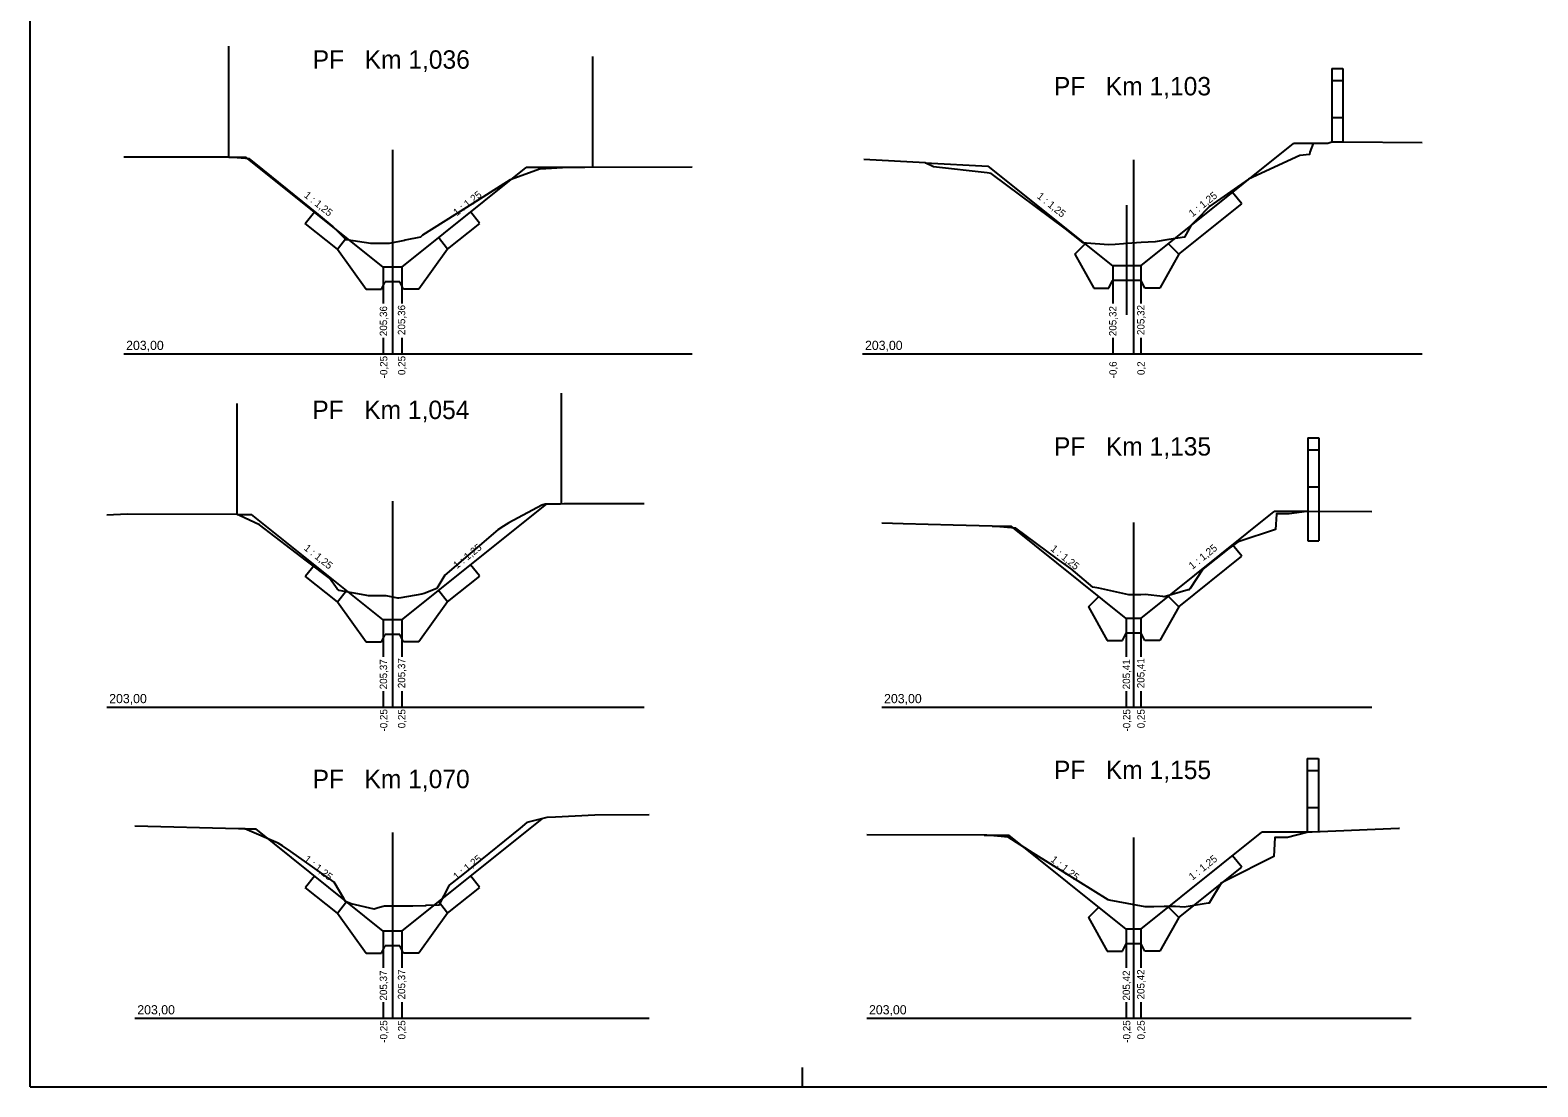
# Model space of a CAD drawing. Extents: x -547174 to -543113, y -1125006 to -1123643.
# Drawn here: x -547152.27 to -547111.27, y -1123769.75 to -1123741.01 of the extents above; entities that cross this region are included whole.
import ezdxf

# ---------------------------------------------------------------- set-up
doc = ezdxf.new("R2010")
doc.units = 0
for name, color, linetype in [('Default', 7, 'Continuous'), ('Profile', 7, 'Continuous'), ('PROFILY NÁVRH', 7, 'Continuous'), ('Section', 7, 'Continuous'), ('STANIČENÍ', 7, 'Continuous')]:
    doc.layers.add(name, color=color, linetype=linetype)

msp = doc.modelspace()

# ---------------------------------------------------------------- linework, layer by layer
at = {"layer": 'Default'}
for points in [[(-547114.415, -1123744.079), (-547116.565, -1123744.061), (-547116.619, -1123744.061), (-547116.866, -1123744.059), (-547116.98, -1123744.096), (-547117.029, -1123744.097), (-547117.326, -1123744.097), (-547117.379, -1123744.096), (-547117.467, -1123744.334), (-547117.474, -1123744.398), (-547117.736, -1123744.425), (-547119.135, -1123745.069), (-547120.184, -1123745.8), (-547120.559, -1123746.178), (-547120.699, -1123746.318), (-547120.699, -1123746.318), (-547120.879, -1123746.645), (-547121.301, -1123746.708), (-547121.679, -1123746.765), (-547122.055, -1123746.792), (-547122.311, -1123746.81), (-547122.762, -1123746.842), (-547122.944, -1123746.855), (-547123.545, -1123746.803), (-547123.636, -1123746.796), (-547124.109, -1123746.415), (-547126.133, -1123744.908), (-547126.247, -1123744.89), (-547127.702, -1123744.732), (-547127.934, -1123744.619), (-547129.597, -1123744.529)], [(-547134.27, -1123744.742), (-547137.186, -1123744.745), (-547137.639, -1123744.746), (-547138.405, -1123744.792), (-547138.416, -1123744.792), (-547139.192, -1123745.073), (-547139.219, -1123745.087), (-547140.407, -1123745.838), (-547141.599, -1123746.592), (-547141.637, -1123746.624), (-547141.643, -1123746.634), (-547141.652, -1123746.638), (-547142.07, -1123746.726), (-547142.087, -1123746.729), (-547142.504, -1123746.817), (-547142.719, -1123746.816), (-547142.727, -1123746.815), (-547142.737, -1123746.815), (-547143.005, -1123746.815), (-547143.671, -1123746.716), (-547143.676, -1123746.715), (-547144.032, -1123746.357), (-547144.034, -1123746.355), (-547144.061, -1123746.335), (-547144.433, -1123746.023), (-547146.132, -1123744.647), (-547146.307, -1123744.516), (-547146.871, -1123744.468), (-547147.045, -1123744.468), (-547149.726, -1123744.469)], [(-547135.575, -1123753.889), (-547137.759, -1123753.895), (-547137.844, -1123753.9), (-547138.262, -1123753.899), (-547138.357, -1123753.934), (-547139.249, -1123754.409), (-547139.398, -1123754.503), (-547139.548, -1123754.599), (-547140.997, -1123755.83), (-547141.214, -1123756.196), (-547141.559, -1123756.334), (-547141.616, -1123756.346), (-547142.189, -1123756.45), (-547142.247, -1123756.462), (-547142.276, -1123756.462), (-547142.593, -1123756.393), (-547143.04, -1123756.393), (-547143.074, -1123756.393), (-547143.159, -1123756.38), (-547143.872, -1123756.25), (-547143.92, -1123756.201), (-547144.13, -1123755.916), (-547144.756, -1123755.443), (-547146.037, -1123754.467), (-547146.579, -1123754.209), (-547146.642, -1123754.182), (-547149.632, -1123754.179), (-547150.186, -1123754.203)], [(-547115.785, -1123754.108), (-547117.521, -1123754.102), (-547117.547, -1123754.104), (-547118.026, -1123754.164), (-547118.035, -1123754.162), (-547118.376, -1123754.162), (-547118.379, -1123754.173), (-547118.4, -1123754.594), (-547119.391, -1123754.915), (-547119.408, -1123754.922), (-547119.667, -1123755.112), (-547120.378, -1123755.669), (-547120.727, -1123756.194), (-547120.753, -1123756.229), (-547120.779, -1123756.234), (-547121.432, -1123756.418), (-547121.469, -1123756.416), (-547121.948, -1123756.362), (-547122.065, -1123756.365), (-547122.389, -1123756.366), (-547123.206, -1123756.187), (-547123.371, -1123756.158), (-547123.962, -1123755.663), (-547124.025, -1123755.615), (-547124.337, -1123755.386), (-547125.466, -1123754.559), (-547125.48, -1123754.558), (-547126.111, -1123754.499), (-547127.171, -1123754.471), (-547128.528, -1123754.434), (-547129.11, -1123754.422)], [(-547135.439, -1123762.352), (-547136.918, -1123762.356), (-547137.983, -1123762.414), (-547138.224, -1123762.423), (-547138.761, -1123762.561), (-547138.943, -1123762.709), (-547139.799, -1123763.401), (-547140.502, -1123763.969), (-547140.874, -1123764.26), (-547140.885, -1123764.279), (-547141.158, -1123764.802), (-547141.5, -1123764.813), (-547141.519, -1123764.82), (-547141.864, -1123764.83), (-547141.891, -1123764.835), (-547141.906, -1123764.832), (-547142.634, -1123764.832), (-547142.811, -1123764.876), (-547142.917, -1123764.919), (-547143.537, -1123764.768), (-547143.699, -1123764.71), (-547143.737, -1123764.621), (-547144.003, -1123764.181), (-547145.184, -1123763.345), (-547145.407, -1123763.192), (-547145.527, -1123763.117), (-547146.432, -1123762.735), (-547146.609, -1123762.735), (-547149.422, -1123762.655)], [(-547115.029, -1123762.725), (-547115.048, -1123762.725), (-547117.407, -1123762.82), (-547117.525, -1123762.822), (-547117.536, -1123762.822), (-547117.554, -1123762.828), (-547118.073, -1123762.962), (-547118.411, -1123762.962), (-547118.417, -1123762.962), (-547118.418, -1123762.968), (-547118.447, -1123763.48), (-547119.743, -1123764.139), (-547119.877, -1123764.211), (-547120.201, -1123764.738), (-547120.209, -1123764.752), (-547120.229, -1123764.756), (-547120.889, -1123764.863), (-547121.12, -1123764.842), (-547121.432, -1123764.847), (-547121.711, -1123764.848), (-547121.944, -1123764.852), (-547122.924, -1123764.669), (-547122.952, -1123764.665), (-547124.99, -1123763.39), (-547125.672, -1123762.961), (-547126.251, -1123762.907), (-547126.319, -1123762.901), (-547126.322, -1123762.901), (-547129.52, -1123762.898)]]:
    msp.add_lwpolyline(points, dxfattribs=at)
at = {"layer": 'Profile'}
for p, q in [((-547152.272, -1123769.746), (-547152.272, -1123740.046)), ((-547131.272, -1123769.218), (-547131.272, -1123769.746)), ((-547152.272, -1123769.746), (-547131.272, -1123769.746)), ((-547131.272, -1123769.746), (-547110.272, -1123769.746))]:
    msp.add_line(p, q, dxfattribs=at)
at = {"layer": 'PROFILY NÁVRH'}
for p, q in [((-547116.866, -1123742.059), (-547116.866, -1123744.059)), ((-547116.866, -1123742.059), (-547116.566, -1123742.059)), ((-547116.566, -1123742.059), (-547116.566, -1123744.061)), ((-547116.866, -1123742.381), (-547116.566, -1123742.381)), ((-547116.866, -1123743.392), (-547116.566, -1123743.392)), ((-547122.061, -1123747.425), (-547117.911, -1123744.096)), ((-547117.379, -1123744.096), (-547117.911, -1123744.096)), ((-547146.871, -1123744.468), (-547146.402, -1123744.468)), ((-547142.668, -1123747.455), (-547146.402, -1123744.468)), ((-547127.934, -1123744.619), (-547126.212, -1123744.712)), ((-547142.168, -1123747.455), (-547138.781, -1123744.746)), ((-547137.639, -1123744.746), (-547138.781, -1123744.746)), ((-547122.83, -1123747.425), (-547126.212, -1123744.712)), ((-547119.319, -1123745.736), (-547119.57, -1123745.424)), ((-547122.445, -1123748.754), (-547122.445, -1123745.773)), ((-547121.03, -1123747.108), (-547119.319, -1123745.736)), ((-547144.792, -1123746.268), (-547144.543, -1123745.955)), ((-547143.917, -1123746.968), (-547144.792, -1123746.268)), ((-547140.918, -1123746.968), (-547140.043, -1123746.268)), ((-547140.047, -1123746.262), (-547140.293, -1123745.955)), ((-547143.917, -1123746.968), (-547143.668, -1123746.655)), ((-547140.918, -1123746.968), (-547141.168, -1123746.655)), ((-547143.917, -1123746.968), (-547143.133, -1123748.055)), ((-547140.918, -1123746.968), (-547141.702, -1123748.055)), ((-547123.861, -1123747.108), (-547123.578, -1123746.825)), ((-547121.03, -1123747.108), (-547121.313, -1123746.825)), ((-547142.168, -1123747.455), (-547142.668, -1123747.455)), ((-547142.668, -1123747.455), (-547142.668, -1123748.447)), ((-547142.168, -1123747.455), (-547142.168, -1123748.447)), ((-547123.861, -1123747.108), (-547123.346, -1123748.025)), ((-547122.061, -1123747.425), (-547122.83, -1123747.425)), ((-547122.83, -1123747.425), (-547122.83, -1123748.447)), ((-547122.061, -1123747.425), (-547122.061, -1123748.447)), ((-547121.03, -1123747.108), (-547121.545, -1123748.025)), ((-547142.718, -1123748.055), (-547142.618, -1123747.855)), ((-547142.218, -1123747.855), (-547142.618, -1123747.855)), ((-547142.118, -1123748.055), (-547142.218, -1123747.855)), ((-547122.934, -1123748.025), (-547122.834, -1123747.825)), ((-547122.057, -1123747.825), (-547122.834, -1123747.825)), ((-547121.957, -1123748.025), (-547122.057, -1123747.825)), ((-547143.133, -1123748.055), (-547142.718, -1123748.055)), ((-547141.702, -1123748.055), (-547142.118, -1123748.055)), ((-547123.346, -1123748.025), (-547122.934, -1123748.025)), ((-547121.545, -1123748.025), (-547121.957, -1123748.025)), ((-547142.668, -1123749.382), (-547142.668, -1123749.815)), ((-547142.168, -1123749.382), (-547142.168, -1123749.815)), ((-547122.83, -1123749.382), (-547122.83, -1123749.815)), ((-547122.061, -1123749.382), (-547122.061, -1123749.815)), ((-547117.521, -1123752.102), (-547117.521, -1123754.903)), ((-547117.521, -1123752.102), (-547117.221, -1123752.102)), ((-547117.221, -1123752.102), (-547117.221, -1123754.903)), ((-547117.521, -1123752.423), (-547117.221, -1123752.423)), ((-547117.521, -1123753.435), (-547117.221, -1123753.435)), ((-547142.168, -1123757.049), (-547138.23, -1123753.899)), ((-547146.642, -1123754.182), (-547146.252, -1123754.182)), ((-547142.668, -1123757.049), (-547146.252, -1123754.182)), ((-547122.061, -1123757.009), (-547118.437, -1123754.102)), ((-547117.521, -1123754.102), (-547118.437, -1123754.102)), ((-547126.111, -1123754.499), (-547125.589, -1123754.499)), ((-547122.461, -1123757.009), (-547125.589, -1123754.499)), ((-547119.319, -1123755.319), (-547119.568, -1123755.009)), ((-547117.521, -1123754.903), (-547117.221, -1123754.903)), ((-547144.788, -1123755.855), (-547144.543, -1123755.549)), ((-547140.047, -1123755.855), (-547140.293, -1123755.549)), ((-547121.03, -1123756.692), (-547119.319, -1123755.319)), ((-547143.917, -1123756.561), (-547144.792, -1123755.861)), ((-547140.918, -1123756.561), (-547140.043, -1123755.861)), ((-547143.917, -1123756.561), (-547143.668, -1123756.249)), ((-547140.918, -1123756.561), (-547141.168, -1123756.249)), ((-547123.491, -1123756.692), (-547123.208, -1123756.409)), ((-547121.03, -1123756.692), (-547121.313, -1123756.409)), ((-547143.917, -1123756.561), (-547143.133, -1123757.649)), ((-547140.918, -1123756.561), (-547141.702, -1123757.649)), ((-547123.491, -1123756.692), (-547122.976, -1123757.609)), ((-547121.03, -1123756.692), (-547121.545, -1123757.609)), ((-547142.168, -1123757.049), (-547142.668, -1123757.049)), ((-547142.668, -1123757.049), (-547142.668, -1123758.05)), ((-547142.168, -1123757.049), (-547142.168, -1123758.05)), ((-547122.061, -1123757.009), (-547122.461, -1123757.009)), ((-547122.461, -1123757.009), (-547122.461, -1123758.05)), ((-547122.061, -1123757.009), (-547122.061, -1123758.05)), ((-547143.133, -1123757.649), (-547142.718, -1123757.649)), ((-547142.718, -1123757.649), (-547142.618, -1123757.449)), ((-547142.218, -1123757.449), (-547142.618, -1123757.449)), ((-547142.118, -1123757.649), (-547142.218, -1123757.449)), ((-547141.702, -1123757.649), (-547142.118, -1123757.649)), ((-547122.976, -1123757.609), (-547122.565, -1123757.609)), ((-547122.565, -1123757.609), (-547122.465, -1123757.409)), ((-547122.057, -1123757.409), (-547122.457, -1123757.409)), ((-547121.957, -1123757.609), (-547122.057, -1123757.409)), ((-547121.545, -1123757.609), (-547121.957, -1123757.609)), ((-547142.668, -1123758.985), (-547142.668, -1123759.419)), ((-547142.168, -1123758.985), (-547142.168, -1123759.419)), ((-547122.461, -1123758.985), (-547122.461, -1123759.419)), ((-547122.061, -1123758.985), (-547122.061, -1123759.419)), ((-547117.536, -1123760.822), (-547117.536, -1123762.822)), ((-547117.536, -1123760.822), (-547117.236, -1123760.822)), ((-547117.236, -1123760.822), (-547117.236, -1123762.813)), ((-547117.536, -1123761.144), (-547117.236, -1123761.144)), ((-547117.536, -1123762.155), (-547117.236, -1123762.155)), ((-547142.168, -1123765.511), (-547138.348, -1123762.455)), ((-547146.432, -1123762.735), (-547146.137, -1123762.735)), ((-547142.668, -1123765.511), (-547146.137, -1123762.735)), ((-547126.322, -1123762.901), (-547125.651, -1123762.901)), ((-547122.461, -1123765.461), (-547125.651, -1123762.901)), ((-547122.061, -1123765.461), (-547118.77, -1123762.821)), ((-547117.466, -1123762.821), (-547118.77, -1123762.821)), ((-547119.318, -1123763.773), (-547119.568, -1123763.461)), ((-547121.028, -1123765.146), (-547119.318, -1123763.773)), ((-547144.788, -1123764.317), (-547144.543, -1123764.011)), ((-547140.047, -1123764.317), (-547140.293, -1123764.011)), ((-547143.917, -1123765.023), (-547144.792, -1123764.323)), ((-547143.917, -1123765.023), (-547143.668, -1123764.711)), ((-547140.918, -1123765.023), (-547141.168, -1123764.711)), ((-547140.918, -1123765.023), (-547140.043, -1123764.323)), ((-547143.917, -1123765.023), (-547143.133, -1123766.111)), ((-547140.918, -1123765.023), (-547141.702, -1123766.111)), ((-547123.491, -1123765.144), (-547123.208, -1123764.861)), ((-547121.028, -1123765.146), (-547121.313, -1123764.861)), ((-547142.168, -1123765.511), (-547142.668, -1123765.511)), ((-547142.668, -1123765.511), (-547142.668, -1123766.512)), ((-547142.168, -1123765.511), (-547142.168, -1123766.512)), ((-547123.491, -1123765.144), (-547122.976, -1123766.061)), ((-547122.061, -1123765.461), (-547122.461, -1123765.461)), ((-547122.461, -1123765.461), (-547122.461, -1123766.512)), ((-547122.061, -1123765.461), (-547122.061, -1123766.512)), ((-547121.03, -1123765.144), (-547121.545, -1123766.061)), ((-547142.718, -1123766.111), (-547142.618, -1123765.911)), ((-547142.218, -1123765.911), (-547142.618, -1123765.911)), ((-547142.118, -1123766.111), (-547142.218, -1123765.911)), ((-547122.565, -1123766.061), (-547122.465, -1123765.861)), ((-547122.057, -1123765.861), (-547122.457, -1123765.861)), ((-547121.957, -1123766.061), (-547122.057, -1123765.861)), ((-547143.133, -1123766.111), (-547142.718, -1123766.111)), ((-547141.702, -1123766.111), (-547142.118, -1123766.111)), ((-547122.976, -1123766.061), (-547122.565, -1123766.061)), ((-547121.545, -1123766.061), (-547121.957, -1123766.061)), ((-547142.668, -1123767.447), (-547142.668, -1123767.881)), ((-547142.168, -1123767.447), (-547142.168, -1123767.881)), ((-547122.461, -1123767.447), (-547122.461, -1123767.881)), ((-547122.061, -1123767.447), (-547122.061, -1123767.881))]:
    msp.add_line(p, q, dxfattribs=at)
at = {"layer": 'Section'}
for p, q in [((-547142.418, -1123744.264), (-547142.418, -1123749.815)), ((-547122.261, -1123744.537), (-547122.261, -1123749.815)), ((-547149.725, -1123749.815), (-547134.264, -1123749.815)), ((-547129.63, -1123749.815), (-547114.416, -1123749.815)), ((-547142.418, -1123753.823), (-547142.418, -1123759.419)), ((-547122.261, -1123754.4), (-547122.261, -1123759.419)), ((-547150.186, -1123759.419), (-547135.575, -1123759.419)), ((-547129.11, -1123759.419), (-547115.785, -1123759.419)), ((-547142.418, -1123762.828), (-547142.418, -1123767.881)), ((-547122.261, -1123762.97), (-547122.261, -1123767.881)), ((-547149.422, -1123767.881), (-547135.439, -1123767.881)), ((-547129.52, -1123767.881), (-547114.711, -1123767.881))]:
    msp.add_line(p, q, dxfattribs=at)
at = {"layer": 'STANIČENÍ'}
for p, q in [((-547146.871, -1123744.468), (-547146.871, -1123741.453)), ((-547136.968, -1123744.745), (-547136.968, -1123741.73)), ((-547146.642, -1123754.182), (-547146.642, -1123751.167)), ((-547137.818, -1123753.895), (-547137.818, -1123750.88))]:
    msp.add_line(p, q, dxfattribs=at)

# ---------------------------------------------------------------- texts
at = {"layer": 'PROFILY NÁVRH'}
for s, rotation, p in [('1 : 1,25', 321.3402, (-547144.842, -1123745.535)), ('1 : 1,25', 321.3402, (-547144.842, -1123745.535)), ('1 : 1,25', 38.6598, (-547140.667, -1123746.079)), ('1 : 1,25', 38.6598, (-547140.667, -1123746.079)), ('1 : 1,25', 38.7413, (-547120.661, -1123746.104)), ('1 : 1,25', 321.2587, (-547124.905, -1123745.562)), ('205,36', 90, (-547142.564, -1123749.334)), ('205,36', 90, (-547142.072, -1123749.304)), ('205,32', 90, (-547122.727, -1123749.334)), ('205,32', 90, (-547121.965, -1123749.304)), ('-0,25', 90, (-547142.558, -1123750.481)), ('0,25', 90, (-547142.067, -1123750.392)), ('-0,6', 90, (-547122.721, -1123750.481)), ('0,2', 90, (-547121.96, -1123750.392)), ('1 : 1,25', 321.3402, (-547144.842, -1123755.128)), ('1 : 1,25', 321.3402, (-547144.842, -1123755.128)), ('1 : 1,25', 38.6598, (-547140.667, -1123755.673)), ('1 : 1,25', 38.6598, (-547140.667, -1123755.673)), ('1 : 1,25', 321.2587, (-547124.535, -1123755.146)), ('1 : 1,25', 38.7413, (-547120.661, -1123755.688)), ('205,37', 90, (-547142.564, -1123758.938)), ('205,37', 90, (-547142.072, -1123758.908)), ('205,41', 90, (-547122.357, -1123758.938)), ('205,41', 90, (-547121.965, -1123758.908)), ('-0,25', 90, (-547142.558, -1123760.085)), ('0,25', 90, (-547142.067, -1123759.996)), ('-0,25', 90, (-547122.351, -1123760.085)), ('0,25', 90, (-547121.96, -1123759.996)), ('1 : 1,25', 321.3402, (-547144.842, -1123763.591)), ('1 : 1,25', 38.6598, (-547140.667, -1123764.135)), ('1 : 1,25', 321.2587, (-547124.535, -1123763.598)), ('1 : 1,25', 38.7413, (-547120.661, -1123764.14)), ('205,37', 90, (-547142.564, -1123767.4)), ('205,37', 90, (-547142.072, -1123767.37)), ('205,42', 90, (-547122.357, -1123767.4)), ('205,42', 90, (-547121.965, -1123767.37)), ('-0,25', 90, (-547142.558, -1123768.547)), ('0,25', 90, (-547142.067, -1123768.458)), ('-0,25', 90, (-547122.351, -1123768.547)), ('0,25', 90, (-547121.96, -1123768.458))]:
    msp.add_text(s, height=0.2, rotation=rotation, dxfattribs=at).set_placement(p)
at = {"layer": 'Section'}
for s, height, p in [('PF   Km 1,036', 0.5, (-547144.587, -1123742.062)), ('PF   Km 1,103', 0.5, (-547124.429, -1123742.787)), ('203,00', 0.25, (-547149.662, -1123749.71)), ('203,00', 0.25, (-547129.566, -1123749.71)), ('PF   Km 1,054', 0.5, (-547144.598, -1123751.588)), ('PF   Km 1,135', 0.5, (-547124.427, -1123752.581)), ('203,00', 0.25, (-547150.122, -1123759.314)), ('203,00', 0.25, (-547129.047, -1123759.314)), ('PF   Km 1,155', 0.5, (-547124.427, -1123761.378)), ('PF   Km 1,070', 0.5, (-547144.591, -1123761.625)), ('203,00', 0.25, (-547149.358, -1123767.776)), ('203,00', 0.25, (-547129.457, -1123767.776))]:
    msp.add_text(s, height=height, dxfattribs=at).set_placement(p)

doc.saveas('drawing.dxf')
